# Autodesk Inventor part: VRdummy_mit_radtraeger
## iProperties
Created: 2007-11
Part Number: VRdummy_mit_radtraeger
Document SubType Name: Modeling
Designer: martin
Manufacturer: Standard
Standards Organization: Custom
Author: martin
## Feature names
1. Extrusion2
2. Extrusion3
3. Extrusion4
